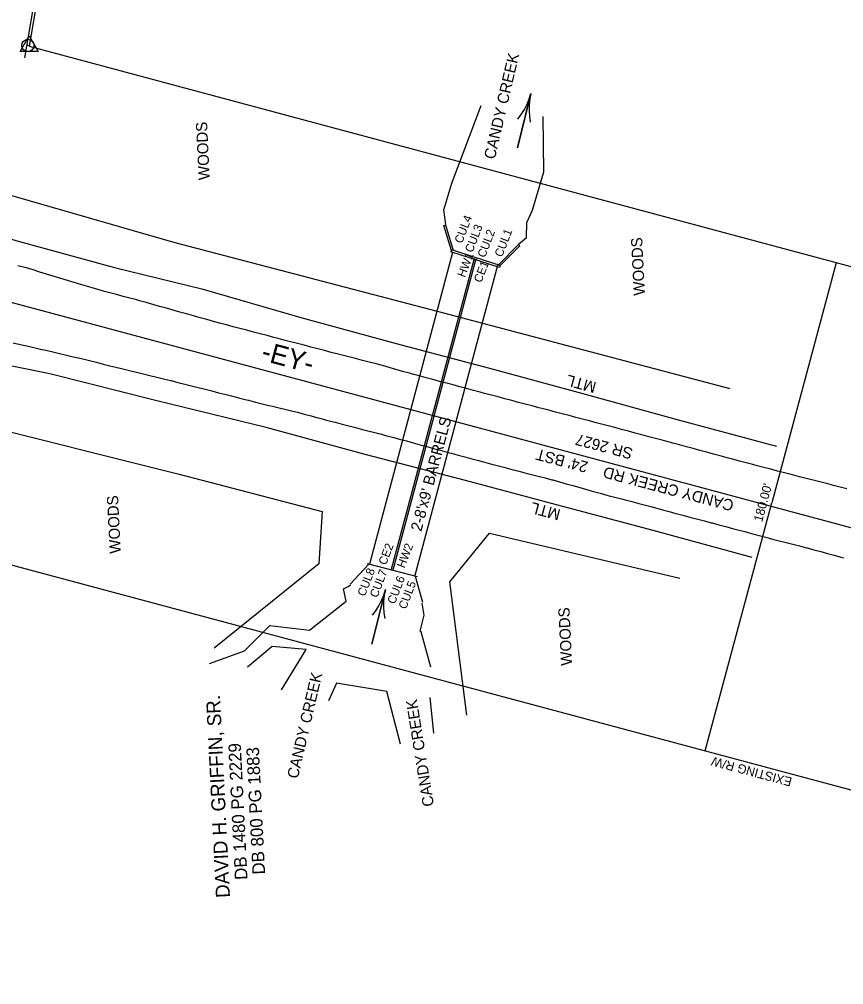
# Model space of a CAD drawing. Extents: x 1806071 to 1809844, y 912722 to 917035.
# Drawn here: x 1807956.1 to 1808250.2, y 913789 to 914133.4 of the extents above; entities that cross this region are included whole.
import ezdxf

# ---------------------------------------------------------------- set-up
doc = ezdxf.new("R2010")
doc.units = 0
for name, color, linetype in [('Exist Guardrail', 7, 'Continuous'), ('Exist Guardrail Text', 7, 'Continuous'), ('Exist Horizontal Alignment', 7, 'Continuous'), ('Exist Horizontal Alignment Direction Label', 7, 'Continuous'), ('Exist Hydro Jurisdictional Stream or Body of Water', 7, 'Continuous'), ('Exist Hydro River Flow Arrow CELL', 7, 'Continuous'), ('Exist Hydro Stream or Body of Water Text', 7, 'Continuous'), ('Exist Other Culture Fence Line', 7, 'Continuous'), ('Exist Property Deed Book Text', 7, 'Continuous'), ('Exist Property Iron Pin CELL', 7, 'Continuous'), ('Exist Property Owner Text', 7, 'Continuous'), ('Exist Right of Way Line', 7, 'Continuous'), ('Exist Right of Way Line Text', 7, 'Continuous'), ('Exist Right of Way Monument CELL', 7, 'Continuous'), ('Exist Right of Way Width CELL', 7, 'Continuous'), ('Exist Roads EOP', 7, 'Continuous'), ('Exist Roads EOP Text', 7, 'Continuous'), ('Exist Structure Major Box Culvert or Tunnel Topo', 7, 'Continuous'), ('Exist Structure Major Box Culvert or Tunnel Topo Text', 7, 'Continuous'), ('Exist Structure Major Deck Tunnel Box Culvert Text', 7, 'Continuous'), ('Exist Structure Minor Head and End Wall', 7, 'Continuous'), ('Exist Vegetation Woods Line', 7, 'Continuous'), ('Exist Vegetation Woods Line Text', 7, 'Continuous')]:
    doc.layers.add(name, color=color, linetype=linetype)

msp = doc.modelspace()

# ---------------------------------------------------------------- linework, layer by layer
at = {"layer": 'Exist Guardrail'}
for points in [[(1807849.43, 914139.23), (1807855.94, 914121.82), (1807864.76, 914105.67), (1807873.1, 914094.2), (1807885.72, 914082.29), (1807901.56, 914072.43), (1807925.08, 914063.59), (1807954.87, 914054.45), (1807990.13, 914044.87), (1808021.28, 914037.26), (1808056.56, 914026.97), (1808090.51, 914017.7), (1808125.58, 914008.42), (1808159.31, 913999.27), (1808191.64, 913990.4), (1808226.24, 913981.05)], [(1808217.52, 913941.37), (1808182.21, 913951.01), (1808147.71, 913960.21), (1808115.34, 913968.86), (1808079.56, 913978.16), (1808044.23, 913987.75), (1808004.74, 913997.35), (1807967.03, 914006.92), (1807934.59, 914013.42), (1807906.7, 914017.75), (1807878.67, 914020.07), (1807861.27, 914019.41), (1807845.25, 914015), (1807829.94, 914006.22), (1807812.69, 913992.29), (1807802.08, 913976.55), (1807792.27, 913954.46), (1807776.81, 913919.09)]]:
    msp.add_lwpolyline(points, dxfattribs=at)
at = {"layer": 'Exist Horizontal Alignment'}
msp.add_line((1808302.48, 913938.64), (1807801.23, 914073.09), dxfattribs=at)
at = {"layer": 'Exist Hydro Jurisdictional Stream or Body of Water'}
msp.add_line((1808103.99, 913878.75), (1808102.69, 913891.45), dxfattribs=at)
for points in [[(1808108.27, 914060.15), (1808107.61, 914065.4), (1808110.41, 914074.96), (1808120.89, 914102.58)], [(1808134.21, 914053.16), (1808137.11, 914055.59), (1808137.13, 914060.92), (1808139.19, 914065.3), (1808143.22, 914079.01), (1808142.96, 914098.71)], [(1808023.96, 913903.58), (1808036.48, 913908.08), (1808045.46, 913917.15), (1808059.61, 913915.41), (1808072.74, 913925.83), (1808071.74, 913930.27), (1808073.38, 913931.1), (1808074.25, 913931.63)], [(1808102.92, 913902.22), (1808099.52, 913914.92), (1808099.13, 913915.14), (1808100.57, 913920.82), (1808099.85, 913925.14)], [(1808049.6, 913894.17), (1808058.4, 913908.54), (1808046.28, 913909.67), (1808037.5, 913902.21)], [(1808092.07, 913874.83), (1808087.27, 913893.61), (1808069.26, 913896.62), (1808066.4, 913890.22)]]:
    msp.add_lwpolyline(points, dxfattribs=at)
at = {"layer": 'Exist Hydro River Flow Arrow CELL'}
for p, q in [((1808136.2, 914097.26), (1808136.2, 914097.26)), ((1808084.3, 913920.23), (1808084.3, 913920.23))]:
    msp.add_line(p, q, dxfattribs=at)
for points in [[(1808133.98, 914097.81), (1808135.2, 914099.45), (1808136.3, 914101.22), (1808137.25, 914103.08), (1808138.04, 914104.99), (1808138.61, 914106.97), (1808133.79, 914087.56), (1808138.61, 914106.97), (1808138.19, 914104.96), (1808138, 914102.89), (1808137.97, 914100.8), (1808138.11, 914098.73), (1808138.42, 914096.71)], [(1808082.08, 913920.78), (1808083.3, 913922.42), (1808084.39, 913924.18), (1808085.34, 913926.05), (1808086.14, 913927.96), (1808086.71, 913929.93), (1808081.89, 913910.52), (1808086.71, 913929.93), (1808086.29, 913927.92), (1808086.09, 913925.86), (1808086.06, 913923.77), (1808086.21, 913921.7), (1808086.52, 913919.67)]]:
    msp.add_lwpolyline(points, dxfattribs=at)
at = {"layer": 'Exist Other Culture Fence Line'}
msp.add_line((1807958.13, 914119.68), (1807974.16, 914214.39), dxfattribs=at)
at = {"layer": 'Exist Property Iron Pin CELL'}
for radius in [2.2, 0.0707]:
    msp.add_circle((1807959.21, 914124.05), radius, dxfattribs=at)
at = {"layer": 'Exist Right of Way Line'}
for p, q in [((1807976.37, 914222.03), (1807959.66, 914123.78)), ((1807959.66, 914123.78), (1808325.79, 914025.57)), ((1807916.86, 913948.56), (1808282.99, 913850.35))]:
    msp.add_line(p, q, dxfattribs=at)
at = {"layer": 'Exist Right of Way Monument CELL'}
msp.add_line((1807959.66, 914123.78), (1807959.66, 914123.78), dxfattribs=at)
msp.add_lwpolyline([(1807956.41, 914121.89), (1807959.66, 914127.53), (1807962.91, 914121.89)], close=True, dxfattribs=at)
at = {"layer": 'Exist Right of Way Width CELL'}
for p in [(1808247.55, 914046.56), (1808200.84, 913872.39)]:
    msp.add_line(p, (1808224.57, 913960.89), dxfattribs=at)
at = {"layer": 'Exist Roads EOP'}
for points in [[(1808251.37, 913965.88), (1808248.95, 913966.5), (1808246.53, 913967.12), (1808244.11, 913967.74), (1808241.68, 913968.36), (1808239.26, 913968.98), (1808236.84, 913969.6), (1808234.42, 913970.22), (1808232, 913970.84), (1808229.58, 913971.46), (1808227.15, 913972.08), (1808226.61, 913972.22), (1808224.19, 913972.85), (1808221.77, 913973.48), (1808219.35, 913974.11), (1808217.83, 913974.51), (1808215.41, 913975.16), (1808213, 913975.81), (1808210.99, 913976.34), (1808208.58, 913976.99), (1808206.17, 913977.64), (1808203.75, 913978.29), (1808201.34, 913978.94), (1808198.92, 913979.59), (1808196.51, 913980.24), (1808194.1, 913980.89), (1808191.68, 913981.54), (1808189.27, 913982.19), (1808187.91, 913982.56), (1808185.49, 913983.2), (1808183.08, 913983.85), (1808180.66, 913984.49), (1808178.24, 913985.14), (1808175.83, 913985.78), (1808173.41, 913986.42), (1808171, 913987.07), (1808168.58, 913987.71), (1808166.17, 913988.36), (1808164.31, 913988.85), (1808161.9, 913989.48), (1808159.48, 913990.12), (1808157.06, 913990.75), (1808154.64, 913991.38), (1808152.22, 913992.02), (1808149.8, 913992.65), (1808147.38, 913993.28), (1808144.97, 913993.91), (1808142.55, 913994.55), (1808141.47, 913994.83), (1808139.05, 913995.47), (1808136.63, 913996.11), (1808134.21, 913996.74), (1808131.8, 913997.38), (1808129.38, 913998.02), (1808126.96, 913998.66), (1808124.54, 913999.29), (1808122.13, 913999.93), (1808120.53, 914000.35), (1808118.12, 914001), (1808115.7, 914001.64), (1808113.29, 914002.29), (1808110.87, 914002.93), (1808108.46, 914003.58), (1808106.04, 914004.22), (1808103.62, 914004.87), (1808101.21, 914005.51), (1808098.79, 914006.16), (1808096.38, 914006.8), (1808095.26, 914007.1), (1808092.86, 914007.79), (1808090.46, 914008.47), (1808088.05, 914009.16), (1808085.65, 914009.84), (1808083.37, 914010.49), (1808080.95, 914011.11), (1808078.53, 914011.72), (1808076.1, 914012.34), (1808073.68, 914012.96), (1808072.27, 914013.32), (1808069.85, 914013.95), (1808067.43, 914014.57), (1808065.01, 914015.2), (1808062.59, 914015.83), (1808060.17, 914016.45), (1808057.75, 914017.08), (1808055.33, 914017.71), (1808052.91, 914018.33), (1808050.49, 914018.96), (1808049.34, 914019.26), (1808046.93, 914019.9), (1808044.51, 914020.54), (1808042.09, 914021.18), (1808039.68, 914021.82), (1808037.26, 914022.46), (1808034.84, 914023.1), (1808032.43, 914023.73), (1808030.01, 914024.37), (1808027.59, 914025.01), (1808025.44, 914025.58), (1808023.03, 914026.26), (1808020.62, 914026.93), (1808018.21, 914027.61), (1808015.81, 914028.28), (1808013.4, 914028.95), (1808010.99, 914029.63), (1808008.58, 914030.3), (1808006.18, 914030.98), (1808003.77, 914031.65), (1808001.36, 914032.32), (1807998.95, 914033), (1807998.03, 914033.26), (1807995.61, 914033.9), (1807993.19, 914034.55), (1807990.78, 914035.19), (1807988.36, 914035.83), (1807986.51, 914036.33), (1807984.11, 914037.04), (1807981.71, 914037.75), (1807979.32, 914038.47), (1807976.92, 914039.18), (1807974.53, 914039.89), (1807972.13, 914040.6), (1807970.63, 914041.05), (1807968.24, 914041.77), (1807965.84, 914042.5), (1807963.45, 914043.22), (1807961.06, 914043.95), (1807958.67, 914044.67), (1807958.04, 914044.86), (1807955.62, 914045.49)], [(1807953.94, 914017.98), (1807956.38, 914017.42), (1807958.81, 914016.86), (1807961.25, 914016.3), (1807963.68, 914015.74), (1807965.6, 914015.3), (1807968.04, 914014.73), (1807970.47, 914014.17), (1807972.91, 914013.6), (1807975.34, 914013.03), (1807977.77, 914012.46), (1807978.77, 914012.23), (1807981.19, 914011.62), (1807983.62, 914011.02), (1807986.04, 914010.41), (1807988.47, 914009.8), (1807990.59, 914009.27), (1807993.02, 914008.68), (1807995.45, 914008.09), (1807997.88, 914007.5), (1808000.3, 914006.91), (1808002.73, 914006.32), (1808005.16, 914005.73), (1808007.59, 914005.14), (1808010.02, 914004.55), (1808010.28, 914004.49), (1808012.71, 914003.87), (1808015.13, 914003.26), (1808017.55, 914002.65), (1808019.98, 914002.03), (1808022.4, 914001.42), (1808024.82, 914000.8), (1808027.24, 914000.19), (1808029.42, 913999.64), (1808031.84, 913999.02), (1808034.27, 913998.4), (1808036.69, 913997.78), (1808037.92, 913997.47), (1808040.34, 913996.86), (1808042.76, 913996.25), (1808045.19, 913995.64), (1808046.42, 913995.34), (1808048.85, 913994.75), (1808051.28, 913994.16), (1808053.71, 913993.58), (1808055.38, 913993.18), (1808057.79, 913992.53), (1808060.21, 913991.89), (1808062.63, 913991.25), (1808063.35, 913991.06), (1808065.76, 913990.43), (1808068.18, 913989.8), (1808068.82, 913989.63), (1808071.24, 913989), (1808073.66, 913988.37), (1808076.08, 913987.74), (1808078.5, 913987.11), (1808080.92, 913986.48), (1808082.42, 913986.09), (1808084.84, 913985.45), (1808087.25, 913984.81), (1808089.67, 913984.17), (1808092.09, 913983.53), (1808094.25, 913982.96), (1808096.66, 913982.3), (1808099.08, 913981.64), (1808101.49, 913980.98), (1808103.9, 913980.33), (1808106.31, 913979.67), (1808108.72, 913979.01), (1808111.13, 913978.35), (1808112.68, 913977.93), (1808115.09, 913977.28), (1808117.51, 913976.63), (1808119.92, 913975.98), (1808121.76, 913975.48), (1808124.18, 913974.85), (1808126.6, 913974.21), (1808129.02, 913973.58), (1808131.44, 913972.94), (1808133.85, 913972.31), (1808133.99, 913972.27), (1808136.41, 913971.65), (1808138.83, 913971.02), (1808141.25, 913970.4), (1808143.67, 913969.77), (1808146.09, 913969.15), (1808146.42, 913969.06), (1808148.83, 913968.39), (1808151.23, 913967.71), (1808153.64, 913967.03), (1808155.68, 913966.45), (1808158.09, 913965.77), (1808160.5, 913965.1), (1808160.94, 913964.97), (1808163.35, 913964.31), (1808165.76, 913963.64), (1808166.58, 913963.42), (1808169, 913962.81), (1808171.43, 913962.19), (1808172.26, 913961.98), (1808174.67, 913961.34), (1808177.09, 913960.7), (1808179.5, 913960.05), (1808181.92, 913959.41), (1808183.12, 913959.09), (1808185.53, 913958.43), (1808187.95, 913957.78), (1808190.36, 913957.12), (1808190.87, 913956.98), (1808193.29, 913956.34), (1808195.71, 913955.71), (1808198.12, 913955.07), (1808200.54, 913954.43), (1808202.96, 913953.8), (1808203.31, 913953.7), (1808205.72, 913953.07), (1808208.14, 913952.43), (1808210.56, 913951.79), (1808212.97, 913951.15), (1808215.39, 913950.51), (1808215.7, 913950.43), (1808218.11, 913949.77), (1808220.52, 913949.11), (1808222.37, 913948.6), (1808224.79, 913947.98), (1808227.21, 913947.36), (1808229.64, 913946.74), (1808232.06, 913946.12), (1808234.48, 913945.5), (1808236.9, 913944.88), (1808237.17, 913944.81), (1808239.59, 913944.16), (1808242, 913943.51), (1808244.41, 913942.86), (1808246.82, 913942.21), (1808249.24, 913941.56), (1808250.26, 913941.28)]]:
    msp.add_lwpolyline(points, dxfattribs=at)
at = {"layer": 'Exist Structure Major Box Culvert or Tunnel Topo'}
for p, q in [((1808081.12, 913939.16), (1808110.76, 914050.34)), ((1808088.89, 913937.19), (1808118.52, 914048.18)), ((1808089.48, 913937.04), (1808119.09, 914048.01)), ((1808126.84, 914045.98), (1808097.18, 913934.95))]:
    msp.add_line(p, q, dxfattribs=at)
at = {"layer": 'Exist Structure Minor Head and End Wall'}
for p, q in [((1808108.2, 914060.02), (1808110.87, 914050.95)), ((1808080.74, 913938.93), (1808074.1, 913931.91)), ((1808100.11, 913925.32), (1808097.43, 913934.56))]:
    msp.add_line(p, q, dxfattribs=at)
for points in [[(1808107.62, 914059.86), (1808108.2, 914060.02)], [(1808110.27, 914050.86), (1808107.62, 914059.86)], [(1808127.65, 914045.55), (1808127.65, 914045.55), (1808119.04, 914048.32), (1808110.37, 914051.11), (1808110.1, 914050.47)], [(1808127.65, 914045.55), (1808127.43, 914044.89), (1808110.1, 914050.47)], [(1808127.05, 914045.74), (1808134.21, 914053.02), (1808134.68, 914052.53), (1808127.61, 914045.56)], [(1808080.21, 913939.22), (1808089.87, 913936.72), (1808098.05, 913934.59)]]:
    msp.add_lwpolyline(points, dxfattribs=at)
at = {"layer": 'Exist Vegetation Woods Line'}
for points in [[(1808209.7, 914001.57), (1808107.61, 914028.54), (1808011.74, 914053.67), (1807944.25, 914072.98), (1807895.34, 914095.43), (1807867.86, 914136.36), (1807863.63, 914175.24), (1807871.41, 914248.45), (1807877.07, 914346.92), (1807874.57, 914413.12), (1807899.31, 914431.8), (1808008.84, 914431.01), (1808040.88, 914453.15), (1808054.97, 914503.44), (1808066.23, 914516.91)], [(1807401.58, 913462.8), (1807479.05, 913516.62), (1807534.26, 913560.78), (1807579.44, 913603.09), (1807630.26, 913607.74), (1807680.67, 913615.06), (1807734.83, 913657.93), (1807768.13, 913689.12), (1807794.8, 913697.71), (1807848.77, 913764.24), (1807844.95, 913813.22), (1807847.89, 913880.15), (1807846.11, 913939.09), (1807839.38, 913962.19), (1807876.02, 913999.26), (1807937, 913990.14), (1808013.16, 913971.16), (1808064.16, 913957.83), (1808063, 913939.08), (1808025.61, 913909.03)], [(1808115.76, 913885.11), (1808109.74, 913932.74), (1808123.84, 913950.06), (1808191.78, 913934.05)]]:
    msp.add_lwpolyline(points, dxfattribs=at)

# ---------------------------------------------------------------- texts
at = {"layer": 'Exist Guardrail Text'}
for rotation, p in [(164.817, (1808162.24, 914003.85)), (165.0349, (1808149.47, 913958.44))]:
    msp.add_text('MTL', height=4, rotation=rotation, dxfattribs=at).set_placement(p)
at = {"layer": 'Exist Horizontal Alignment Direction Label'}
msp.add_text('-EY-', height=7, rotation=344.9856, dxfattribs=at).set_placement((1808042.07, 914011.87))
at = {"layer": 'Exist Hydro Stream or Body of Water Text'}
for rotation, p in [(76.8624, (1808125.72, 914083.19)), (76.8624, (1808055.47, 913862.27)), (99.1249, (1808104.08, 913852.87))]:
    msp.add_text('CANDY CREEK', height=4, rotation=rotation, dxfattribs=at).set_placement(p)
at = {"layer": 'Exist Property Deed Book Text'}
for s, p in [('DB 1480 PG 2229', (1808037.55, 913826.51)), ('DB 800 PG 1883', (1808043.83, 913828.41))]:
    msp.add_text(s, height=4.5, rotation=92.8422, dxfattribs=at).set_placement(p)
at = {"layer": 'Exist Property Owner Text'}
msp.add_text('DAVID H. GRIFFIN, SR.', height=5, rotation=92.8422, dxfattribs=at).set_placement((1808031.28, 913820.1))
at = {"layer": 'Exist Right of Way Line Text'}
msp.add_text('EXISTING R/W', height=3.2, rotation=164.9856, dxfattribs=at).set_placement((1808232, 913862.74))
at = {"layer": 'Exist Right of Way Width CELL'}
msp.add_text("180.00'", height=3.2, rotation=74.9856, dxfattribs=at).set_placement((1808221.11, 913953.86))
at = {"layer": 'Exist Roads EOP Text'}
for s, p in [('SR 2627', (1808175.29, 913980.23)), ("CANDY CREEK RD    24' BST", (1808211.32, 913961.7))]:
    msp.add_text(s, height=4, rotation=165.2267, dxfattribs=at).set_placement(p)
at = {"layer": 'Exist Structure Major Box Culvert or Tunnel Topo Text'}
msp.add_text("2-8'x9' BARRELS", height=4, rotation=75.089, dxfattribs=at).set_placement((1808099.52, 913950.46))
at = {"layer": 'Exist Structure Major Deck Tunnel Box Culvert Text'}
for s, p in [('CUL4', (1808114.03, 914053.2)), ('CUL3', (1808117.77, 914049.93)), ('CUL2', (1808122.23, 914048.12)), ('CUL1', (1808128.34, 914048.34)), ('HW1', (1808115.07, 914041.09)), ('CE1', (1808120.91, 914039.2)), ('CE2', (1808086.91, 913938.46)), ('HW2', (1808093.5, 913937.41)), ('CUL8', (1808079.4, 913927.3)), ('CUL7', (1808083.82, 913926.84)), ('CUL6', (1808090.08, 913924.55)), ('CUL5', (1808094.06, 913922.72))]:
    msp.add_text(s, height=3, rotation=68.9007, dxfattribs=at).set_placement(p)
at = {"layer": 'Exist Vegetation Woods Line Text'}
for p in [(1808024.11, 914076.15), (1808179.33, 914034.93), (1807992.37, 913942.87), (1808153.39, 913902.92)]:
    msp.add_text('WOODS', height=4, rotation=92.8422, dxfattribs=at).set_placement(p)

doc.saveas('drawing.dxf')
